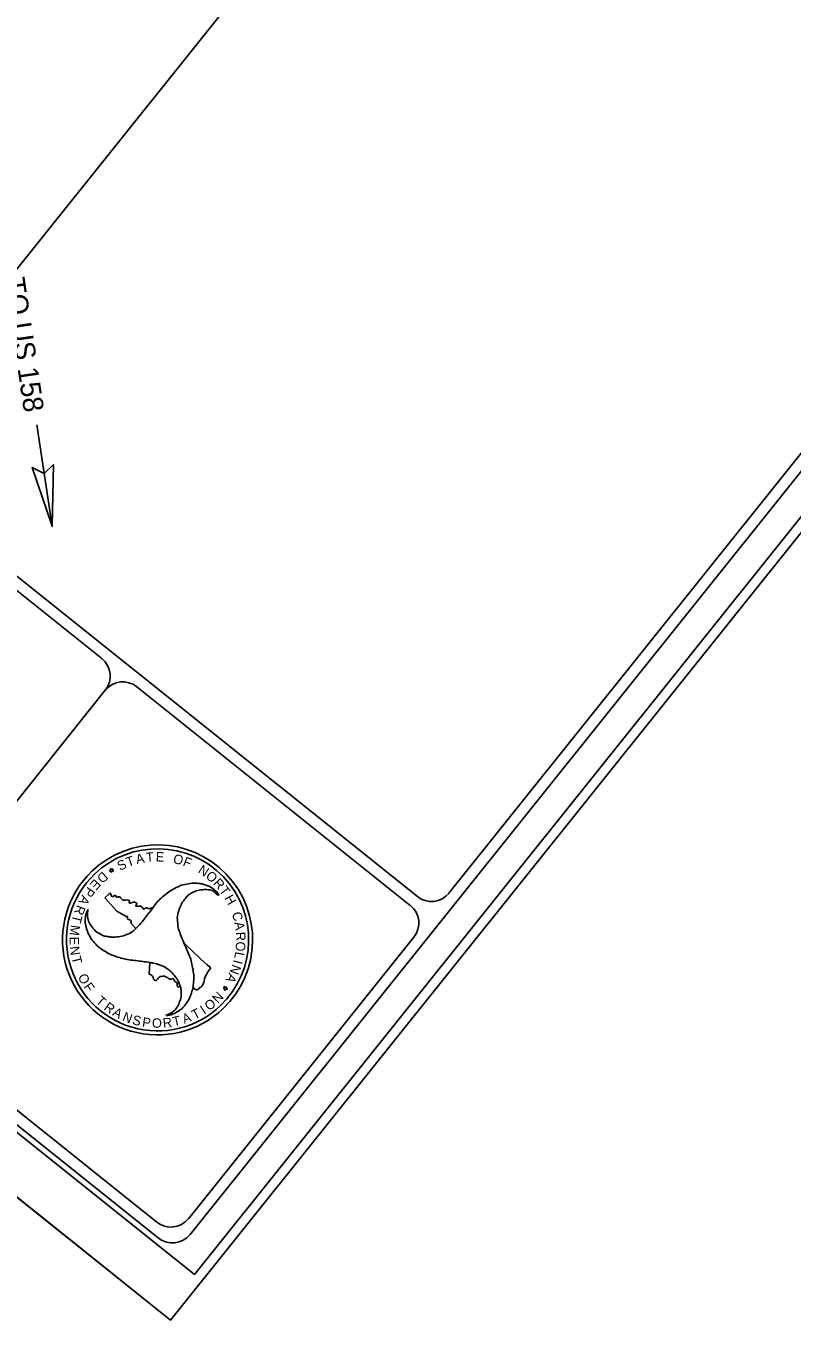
# Model space of a CAD drawing. Extents: x 1732765 to 1738218, y 913652 to 917906.
# Drawn here: x 1735266 to 1735946, y 913906 to 915055 of the extents above; entities that cross this region are included whole.
import ezdxf

# ---------------------------------------------------------------- set-up
doc = ezdxf.new("R2010")
doc.units = 0
for name, color, linetype in [('Old_Level_9', 7, 'Continuous'), ('Prop DSN Text', 7, 'Continuous'), ('Prop Rip Rap Related Quantities Text', 7, 'Continuous'), ('Prop Terminator CELL', 7, 'Continuous'), ('Sheet Cutting Line CELL', 7, 'Continuous'), ('Sheet Data Field CELL', 7, 'Continuous'), ('Sheet Plot Border Inside CELL', 7, 'Continuous'), ('Sheet Title CELL', 7, 'Continuous')]:
    doc.layers.add(name, color=color, linetype=linetype)

msp = doc.modelspace()

# ---------------------------------------------------------------- linework, layer by layer
at = {"layer": 'Old_Level_9'}
msp.add_line((1735276.1, 914700.7), (1735289.8, 914610.8), dxfattribs=at)
at = {"layer": 'Prop Rip Rap Related Quantities Text'}
msp.add_lwpolyline([(1733985, 915648.7), (1733976.3, 915637.9), (1735147.5, 914700.6), (1735803.5, 915520.4)], dxfattribs=at)
at = {"layer": 'Prop Terminator CELL'}
msp.add_lwpolyline([(1735290.9, 914665.6), (1735289.8, 914610.8), (1735272.1, 914663), (1735282.7, 914657.6)], close=True, dxfattribs=at)
at = {"layer": 'Sheet Cutting Line CELL'}
msp.add_line((1732765.3, 916010.8), (1735394.8, 913906.4), dxfattribs=at)
at = {"layer": 'Sheet Data Field CELL'}
msp.add_lwpolyline([(1736769.5, 915624), (1734139.9, 917728.5), (1732765.3, 916010.8), (1735394.8, 913906.4)], close=True, dxfattribs=at)
at = {"layer": 'Sheet Plot Border Inside CELL'}
msp.add_lwpolyline([(1732813.6, 916029.6), (1735415.9, 913947), (1736734.4, 915594.6), (1734132.1, 917677.2)], close=True, dxfattribs=at)
at = {"layer": 'Sheet Title CELL'}
for p, q in [((1733396.2, 916056.6), (1735613.6, 914282.1)), ((1735021.7, 914742.9), (1735333.7, 914493.3)), ((1735136.9, 914215.3), (1735336.8, 914465.2)), ((1735364.9, 914468.3), (1735607.3, 914274.3)), ((1735340.4, 914305.1), (1735341.7, 914305.8)), ((1735341.8, 914304.9), (1735340.4, 914305.1)), ((1735341.7, 914305.8), (1735341.5, 914307.2)), ((1735341.5, 914307.2), (1735342.6, 914306.2)), ((1735342, 914303.4), (1735341.8, 914304.9)), ((1735342.7, 914304.7), (1735342, 914303.4)), ((1735342.6, 914306.2), (1735343.8, 914306.8)), ((1735344.2, 914304.5), (1735342.7, 914304.7)), ((1735343.8, 914306.8), (1735343.2, 914305.5)), ((1735343.2, 914305.5), (1735344.2, 914304.5)), ((1735336.4, 914281.2), (1735340.2, 914284.6)), ((1735347, 914269.2), (1735336.4, 914281.2)), ((1735437.7, 914283.5), (1735437.4, 914283.5)), ((1735437.7, 914283.5), (1735437.4, 914283.5)), ((1735355.3, 914264.5), (1735347, 914269.2)), ((1735364, 914253.8), (1735359.4, 914258.7)), ((1735406.5, 914241.2), (1735406.5, 914241.2)), ((1735375.7, 914213.3), (1735376.3, 914223.7)), ((1735376.3, 914223.7), (1735376.3, 914223.7)), ((1735442.6, 914201.1), (1735441.3, 914200.5)), ((1735441.3, 914200.5), (1735442.7, 914200.3)), ((1735443.4, 914201.5), (1735442.4, 914202.6)), ((1735442.4, 914202.6), (1735442.6, 914201.1)), ((1735442.7, 914200.3), (1735442.9, 914198.8)), ((1735442.9, 914198.8), (1735443.6, 914200.1)), ((1735444.7, 914202.2), (1735443.4, 914201.5)), ((1735443.6, 914200.1), (1735445.1, 914199.9)), ((1735444, 914200.9), (1735444.7, 914202.2)), ((1735445.1, 914199.9), (1735444, 914200.9)), ((1735441.6, 914182.8), (1735441.6, 914182.8))]:
    msp.add_line(p, q, dxfattribs=at)
for points in [[(1733072.9, 915828.7), (1735383.9, 913979.1)], [(1735412, 913982.3), (1736699.2, 915590.6)], [(1735641.6, 914285.2), (1736685.1, 915589.1)], [(1735410.5, 913996.3), (1735610.4, 914246.2)], [(1735140, 914187.2), (1735382.4, 913993.2)]]:
    msp.add_lwpolyline(points, dxfattribs=at)
for centre, radius, start, end in [((1735321.2, 914477.7), 20, 321.3297, 51.3297), ((1735352.4, 914452.7), 20, 51.3297, 141.3297), ((1735383.2, 914243.8), 84.3, 313.7508, 133.7508), ((1735383.2, 914243.8), 80.8, 313.7508, 133.7508), ((1735383.2, 914243.8), 84.3, 133.7508, 313.7508), ((1735383.2, 914243.8), 80.8, 133.7508, 313.7508), ((1735626.1, 914297.8), 20, 231.3297, 321.3297), ((1735594.9, 914258.7), 20, 321.3297, 51.3297), ((1735721.7, 914554.9), 444.7, 219.4293, 219.5289), ((1735721.7, 914554.9), 444.7, 224.8684, 229.0744), ((1735394.9, 914008.9), 20, 231.3297, 321.3297), ((1735396.5, 913994.8), 20, 231.3297, 321.3297)]:
    msp.add_arc(centre, radius, start, end, dxfattribs=at)
for points in [[(1735437.4, 914283.5), (1735436.5, 914285.2), (1735432.5, 914289.1), (1735427.2, 914292), (1735426.7, 914292.1), (1735423.6, 914293.1), (1735419.9, 914293.8), (1735413.6, 914294.1), (1735407.3, 914292.9), (1735404.7, 914292.4), (1735402, 914291.2), (1735396.4, 914288.4), (1735391.6, 914285.1), (1735386.4, 914280.8), (1735382.2, 914276.6), (1735378.6, 914271.7), (1735374.9, 914266.8), (1735371.3, 914262.1), (1735367.4, 914257.3), (1735363.1, 914253.1), (1735362.7, 914252.7), (1735357.3, 914249.1), (1735351.5, 914247.1), (1735345.7, 914246.2), (1735342.8, 914246.1), (1735339.2, 914246.7), (1735337.2, 914246.9), (1735333.2, 914248.4), (1735328.2, 914251.6), (1735324.5, 914255.9), (1735322, 914260.4), (1735321, 914265.5), (1735321.5, 914270.8)], [(1735340.2, 914284.6), (1735340.4, 914285), (1735341.4, 914284.8), (1735342.3, 914282.4), (1735343.9, 914282.3), (1735344.6, 914283), (1735346, 914283), (1735346.9, 914281.6), (1735349.3, 914281.9), (1735350.4, 914281.1), (1735352.4, 914279.1), (1735357.2, 914279), (1735358.3, 914278.1), (1735357.9, 914277.2), (1735358.4, 914276.4), (1735361.4, 914277.3), (1735362, 914277.3), (1735364.6, 914276.2), (1735364.7, 914275.3), (1735363.9, 914274.3), (1735364, 914273.8), (1735365.1, 914273.6), (1735366.9, 914273.8), (1735369.3, 914273), (1735370.8, 914271), (1735372.5, 914272.1), (1735375.9, 914271.4), (1735377.2, 914271.8), (1735378.2, 914272.5)], [(1735390.5, 914176.7), (1735392.4, 914176.7), (1735397.8, 914178.3), (1735402.9, 914181.4), (1735403.4, 914181.7), (1735405.7, 914183.9), (1735408.2, 914186.8), (1735411.6, 914192.1), (1735413.7, 914198.1), (1735414.6, 914200.6), (1735414.9, 914203.7), (1735415.3, 914209.9), (1735414.9, 914215.7), (1735413.6, 914222.3), (1735412.1, 914228), (1735409.7, 914233.6), (1735407.3, 914239.3), (1735405.1, 914244.7), (1735402.8, 914250.5), (1735401.3, 914256.3), (1735401.3, 914256.9), (1735400.7, 914263.4), (1735402, 914269.5), (1735404, 914274.9), (1735405.5, 914277.4), (1735407.7, 914280.2), (1735408.9, 914281.9), (1735412.2, 914284.6), (1735417.5, 914287.3), (1735423, 914288.3), (1735428.2, 914288.3), (1735433.2, 914286.6), (1735437.4, 914283.5), (1735437.7, 914283.5)], [(1735321.5, 914270.8), (1735320.6, 914269.1), (1735319.2, 914263.6), (1735319.3, 914257.7), (1735319.4, 914257.2), (1735320.1, 914253.9), (1735321.4, 914250.4), (1735324.3, 914244.8), (1735328.4, 914240), (1735330.2, 914238), (1735332.7, 914236.2), (1735337.8, 914232.8), (1735343, 914230.2), (1735349.4, 914228), (1735355, 914226.5), (1735361.1, 914225.7), (1735367.3, 914225), (1735373.2, 914224.2), (1735379.2, 914223.2), (1735385, 914221.6), (1735385.6, 914221.4), (1735391.5, 914218.5), (1735396.1, 914214.5), (1735399.7, 914210.1), (1735401.3, 914207.5), (1735402.5, 914204.2), (1735403.4, 914202.2), (1735404.1, 914198), (1735403.8, 914192.1), (1735401.9, 914186.8), (1735399.3, 914182.4), (1735395.3, 914178.9), (1735390.5, 914176.7)], [(1735359.4, 914258.7), (1735359.9, 914260), (1735359.2, 914261.2), (1735357.4, 914261.8), (1735356.5, 914262.8), (1735356.3, 914264.6), (1735355.3, 914264.5)], [(1735378.7, 914271.9), (1735378.6, 914271.7), (1735374.9, 914266.8), (1735371.3, 914262.1), (1735367.4, 914257.3), (1735364, 914253.8)], [(1735414.8, 914201.7), (1735414.9, 914203.7), (1735415.3, 914209.9), (1735414.9, 914215.7), (1735413.6, 914222.3), (1735412.1, 914228), (1735409.7, 914233.6), (1735407.3, 914239.3), (1735406.5, 914241.2)], [(1735376.3, 914223.7), (1735379.2, 914223.2), (1735385, 914221.6), (1735385.6, 914221.4), (1735391.5, 914218.5), (1735396.1, 914214.5), (1735399.7, 914210.1), (1735401.3, 914207.5), (1735402.5, 914204.2), (1735403.3, 914202.4)], [(1735430.3, 914218.9), (1735427.1, 914214.1), (1735424.4, 914207.4), (1735423.1, 914203.5), (1735420.8, 914201.4), (1735417.6, 914199.4), (1735414.8, 914201.7)], [(1735403.3, 914202.4), (1735401.7, 914201.9), (1735400.7, 914202.7), (1735400.5, 914205.6), (1735398.2, 914207.2), (1735397.8, 914208.6), (1735397.3, 914209.2), (1735394.1, 914208.9), (1735391.8, 914210.4), (1735386.5, 914211.4), (1735384.5, 914210.7), (1735381.8, 914207.7), (1735380.5, 914207.9), (1735379.7, 914209), (1735378.6, 914211.7), (1735375.7, 914213.3)]]:
    msp.add_spline(points, degree=3, dxfattribs=at)

# ---------------------------------------------------------------- texts
at = {"layer": 'Prop DSN Text'}
msp.add_text('TO US 158', height=18, rotation=278.3862, dxfattribs=at).set_placement((1735247.3, 914830.1))
at = {"layer": 'Sheet Title CELL'}
for s, height, rotation, p in [('A', 8.44, 12.0786, (1735364.8, 914310.9)), ('T', 8.39, 5.0234, (1735373.3, 914312.7)), ('E', 8.38, 357.9077, (1735381.5, 914313.4)), ('O', 8.42, 345.9684, (1735396.4, 914312.1)), ('S', 8.4, 25.5071, (1735349.8, 914304.9)), ('T', 8.43, 19.1309, (1735357, 914308.3)), ('F', 8.43, 338.8215, (1735405, 914309.9)), ('N', 8.41, 326.7346, (1735418.4, 914303.9)), ('E', 8.37, 227.8917, (1735327.4, 914298.4)), ('D', 8.41, 221.6038, (1735334.6, 914304.9)), ('O', 8.43, 319.2365, (1735425.2, 914299.4)), ('R', 8.41, 312.6265, (1735432, 914293.6)), ('P', 8.41, 235.4241, (1735321.4, 914291.5)), ('T', 8.43, 305.9769, (1735437.4, 914287.6)), ('R', 8.41, 249.0853, (1735311.8, 914275.3)), ('A', 8.4, 242.0167, (1735316.3, 914284.1)), ('H', 8.4, 298.8922, (1735442.2, 914280.9)), ('T', 8.4, 255.7358, (1735308.5, 914266.6)), ('C', 8.39, 286.5498, (1735448.9, 914267.3)), ('M', 8.39, 262.9709, (1735306.3, 914257.3)), ('A', 8.4, 279.0528, (1735451.2, 914259.2)), ('E', 8.39, 270.4376, (1735305.2, 914246.6)), ('O', 8.43, 265.5693, (1735452.9, 914242.6)), ('R', 8.4, 272.6889, (1735452.6, 914250.7)), ('N', 8.43, 277.4092, (1735305.3, 914237.6)), ('T', 8.4, 284.2512, (1735306.7, 914228.2)), ('L', 8.39, 259.3356, (1735452.3, 914233.7)), ('N', 8.41, 249.6461, (1735449.7, 914222.6)), ('I', 8.42, 255.3462, (1735450.8, 914226.6)), ('O', 8.41, 297.5549, (1735312.2, 914211.1)), ('F', 8.4, 304.7201, (1735317.1, 914202.2)), ('A', 8.41, 242.2142, (1735446.7, 914214.9)), ('T', 8.38, 317.6293, (1735327.7, 914188.7)), ('N', 8.41, 45.9589, (1735436.8, 914186.8)), ('R', 8.42, 324.586, (1735334.9, 914182.3)), ('A', 8.38, 331.3391, (1735342.5, 914177.1)), ('T', 8.4, 27.9254, (1735416.1, 914172.8)), ('I', 8.43, 33.5753, (1735424.5, 914177.3)), ('O', 8.38, 38.7109, (1735429, 914180.4)), ('N', 8.38, 338.3707, (1735351.3, 914172.4)), ('S', 8.37, 345.5812, (1735360.2, 914169.1)), ('P', 8.41, 352.773, (1735369.2, 914166.8)), ('O', 8.43, 359.465, (1735378.2, 914165.8)), ('R', 8.42, 6.6541, (1735388.3, 914165.7)), ('T', 8.38, 12.7539, (1735397.6, 914166.9)), ('A', 8.43, 20.841, (1735406.8, 914169.2))]:
    msp.add_text(s, height=height, rotation=rotation, dxfattribs=at).set_placement(p)

doc.saveas('drawing.dxf')
